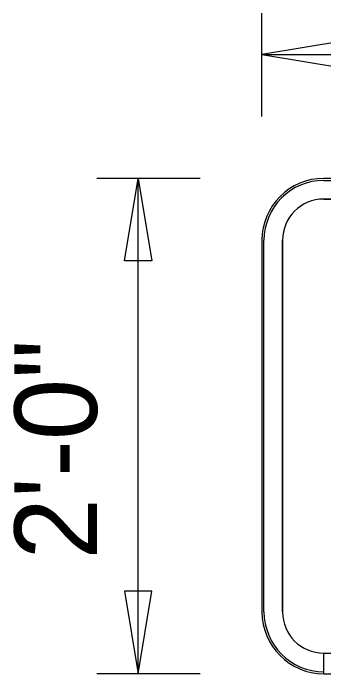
# Model space of a CAD drawing. Extents: x 17890628 to 17890844, y 17897508 to 17897992.
# Drawn here: x 17890811.09 to 17890813.6, y 17897544.34 to 17897549.68 of the extents above; entities that cross this region are included whole.
import ezdxf

# ---------------------------------------------------------------- set-up
doc = ezdxf.new("R2010")
doc.units = 0
for name, color, linetype in [('GSBWFill', 7, 'Continuous'), ('GSColorFill', 7, 'Continuous'), ('GSDims', 7, 'Continuous'), ('GSOutline', 7, 'Continuous')]:
    doc.layers.add(name, color=color, linetype=linetype)

msp = doc.modelspace()

# ---------------------------------------------------------------- linework, layer by layer
at = {"layer": 'GSBWFill'}
for p, q in [((17890820.5961, 17897548.3429), (17890813.5961, 17897548.3429)), ((17890813.5961, 17897548.1762), (17890820.5961, 17897548.1762)), ((17890813.0961, 17897547.8429), (17890813.0961, 17897544.8429)), ((17890813.2628, 17897544.8429), (17890813.2628, 17897547.8429)), ((17890813.5961, 17897544.3429), (17890813.5961, 17897544.5096))]:
    msp.add_line(p, q, dxfattribs=at)
for centre, radius, start, end in [((17890813.5961, 17897547.8429), 0.5, 90, 180), ((17890813.5961, 17897547.8429), 0.3333, 90, 180), ((17890813.5961, 17897544.8429), 0.5, 180, 270), ((17890813.5961, 17897544.8429), 0.3333, 180, 270)]:
    msp.add_arc(centre, radius, start, end, dxfattribs=at)
at = {"layer": 'GSColorFill'}
for p, q in [((17890820.5961, 17897548.3429), (17890813.5961, 17897548.3429)), ((17890820.5961, 17897548.3429), (17890813.5961, 17897548.3429)), ((17890820.5961, 17897548.3429), (17890813.5961, 17897548.3429)), ((17890813.5961, 17897548.3262), (17890820.5961, 17897548.3262)), ((17890813.5961, 17897548.1762), (17890820.5961, 17897548.1762)), ((17890813.0961, 17897547.8429), (17890813.0961, 17897544.8429)), ((17890813.0961, 17897547.8429), (17890813.0961, 17897544.8429)), ((17890813.0961, 17897547.8429), (17890813.0961, 17897544.8429)), ((17890813.1128, 17897544.8429), (17890813.1128, 17897547.8429)), ((17890813.2628, 17897544.8429), (17890813.2628, 17897547.8429)), ((17890813.5961, 17897544.3429), (17890813.5961, 17897544.5096)), ((17890813.5961, 17897544.3429), (17890813.5961, 17897544.3596)), ((17890813.5961, 17897544.3429), (17890820.5961, 17897544.3429))]:
    msp.add_line(p, q, dxfattribs=at)
for centre, radius, start, end in [((17890813.5961, 17897547.8429), 0.5, 90, 180), ((17890813.5961, 17897547.8429), 0.5, 90, 180), ((17890813.5961, 17897547.8429), 0.5, 90, 180), ((17890813.5961, 17897547.8429), 0.4833, 90, 180), ((17890813.5961, 17897547.8429), 0.3333, 90, 180), ((17890813.5961, 17897544.8429), 0.5, 180, 270), ((17890813.5961, 17897544.8429), 0.5, 180, 270), ((17890813.5961, 17897544.8429), 0.5, 180, 270), ((17890813.5961, 17897544.8429), 0.4833, 180, 270), ((17890813.5961, 17897544.8429), 0.3333, 180, 270)]:
    msp.add_arc(centre, radius, start, end, dxfattribs=at)
at = {"layer": 'GSDims'}
for p, q in [((17890813.0961, 17897548.8429), (17890813.0961, 17897549.6762)), ((17890813.0961, 17897549.3429), (17890821.0961, 17897549.3429)), ((17890812.5961, 17897548.3429), (17890811.7628, 17897548.3429)), ((17890812.0961, 17897544.3429), (17890812.0961, 17897548.3429)), ((17890812.5961, 17897544.3429), (17890811.7628, 17897544.3429))]:
    msp.add_line(p, q, dxfattribs=at)
for points in [[(17890813.0961, 17897549.3429), (17890813.7628, 17897549.2318), (17890813.7628, 17897549.454)], [(17890812.0961, 17897548.3429), (17890812.2072, 17897547.6762), (17890811.985, 17897547.6762)], [(17890812.0961, 17897544.3429), (17890812.2072, 17897545.0096), (17890811.985, 17897545.0096)]]:
    msp.add_lwpolyline(points, close=True, dxfattribs=at)
at = {"layer": 'GSOutline'}
for p, q in [((17890820.5961, 17897548.3429), (17890813.5961, 17897548.3429)), ((17890820.5961, 17897548.1762), (17890813.5961, 17897548.1762)), ((17890813.0961, 17897547.8429), (17890813.0961, 17897544.8429)), ((17890813.2628, 17897547.8429), (17890813.2628, 17897544.8429)), ((17890813.5961, 17897544.5096), (17890820.5961, 17897544.5096)), ((17890813.5961, 17897544.3429), (17890820.5961, 17897544.3429))]:
    msp.add_line(p, q, dxfattribs=at)
for centre, radius, start, end in [((17890813.5961, 17897547.8429), 0.5, 90, 180), ((17890813.5961, 17897547.8429), 0.3333, 90, 180), ((17890813.5961, 17897544.8429), 0.5, 180, 270), ((17890813.5961, 17897544.8429), 0.3333, 180, 270)]:
    msp.add_arc(centre, radius, start, end, dxfattribs=at)

# ---------------------------------------------------------------- texts
at = {"layer": 'GSDims'}
msp.add_text('2\'-0"', height=0.66667, rotation=90, dxfattribs=at).set_placement((17890811.7628, 17897545.2659))

doc.saveas('drawing.dxf')
